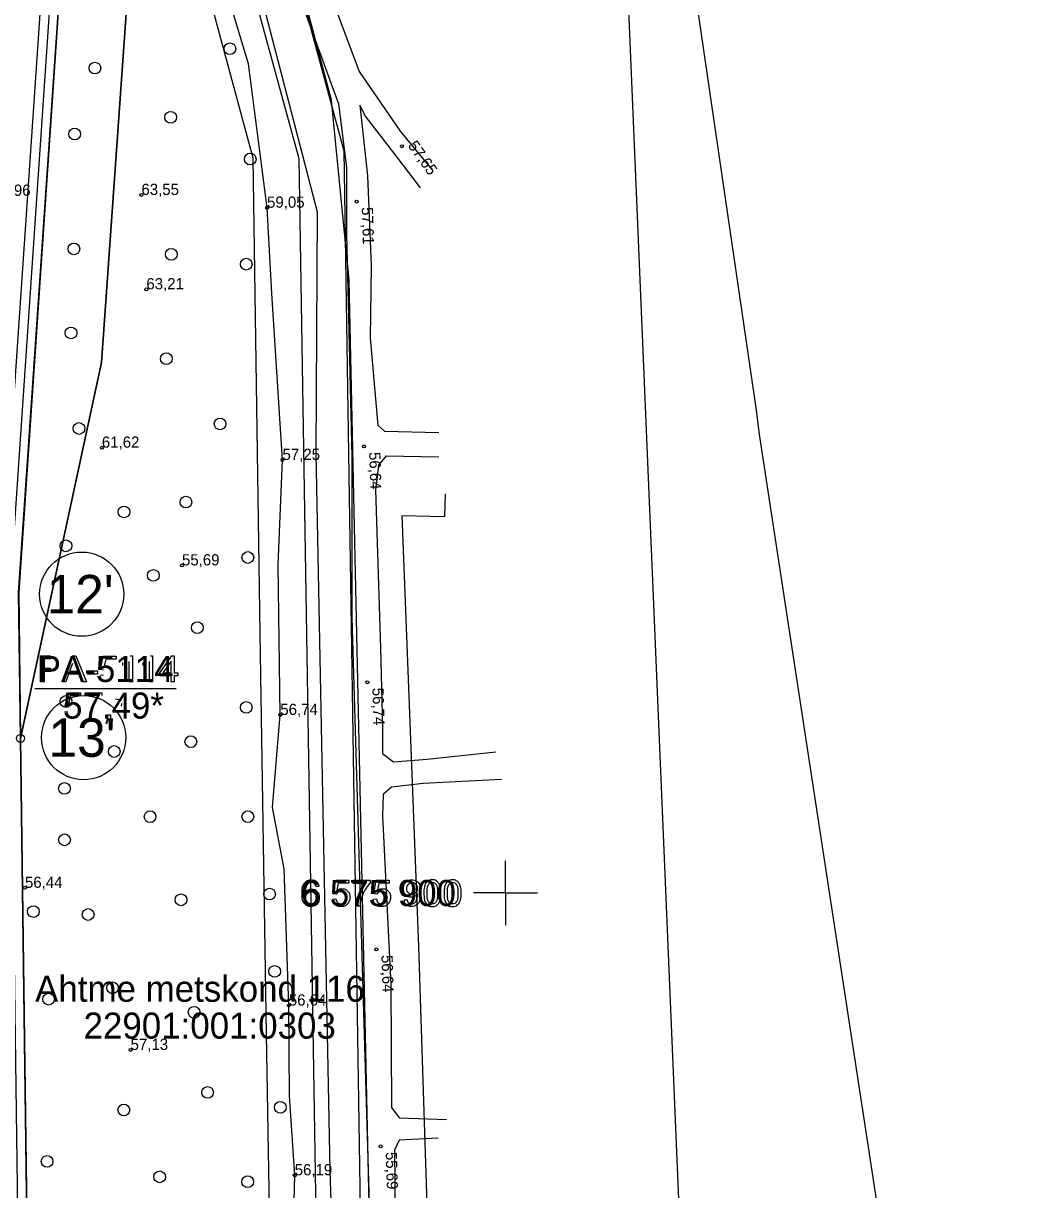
# Model space of a CAD drawing. Extents: x 700746 to 706058, y 6570320 to 6580460.
# Drawn here: x 703294.7 to 703516.5, y 6575835.2 to 6576090 of the extents above; entities that cross this region are included whole.
import ezdxf

# ---------------------------------------------------------------- set-up
doc = ezdxf.new("R2010")
doc.units = 0
for name, color, linetype in [('GEOLPUNKT', 7, 'Continuous'), ('HALJASTUS', 7, 'Continuous'), ('illumineerimisjooned', 7, 'Continuous'), ('Kaitsevöönd', 7, 'Continuous'), ('kataster', 7, 'Continuous'), ('Kataster tekst', 7, 'Continuous'), ('KORGUS-EH2000', 7, 'Continuous'), ('KPOHULIIN', 7, 'Continuous'), ('PIIR', 7, 'Continuous'), ('Plokid', 7, 'Continuous'), ('RELJEEF', 7, 'Continuous'), ('TEE', 7, 'Continuous'), ('Tmaad_maeeraldised_kehtivad', 7, 'Continuous'), ('VORK', 7, 'Continuous'), ('VTRASS', 7, 'Continuous'), ('VWX2_MV_PLOKK', 7, 'Continuous')]:
    doc.layers.add(name, color=color, linetype=linetype)

msp = doc.modelspace()

# ---------------------------------------------------------------- linework, layer by layer
at = {"layer": 'GEOLPUNKT'}
msp.add_line((703297.15, 6575944.7), (703328.06, 6575944.7), dxfattribs=at)
msp.add_line((703297.15, 6575944.7), (703328.06, 6575944.7), dxfattribs=at)
for points in [[(703298.44, 6575946.1), (703298.44, 6575951.8), (703300.59, 6575951.8)], [(703300.65, 6575951.12), (703299.19, 6575951.12), (703299.19, 6575949.09)], [(703303.13, 6575946.1), (703305.32, 6575951.8), (703306.13, 6575951.8), (703308.46, 6575946.1), (703307.6, 6575946.1), (703306.94, 6575947.82), (703304.55, 6575947.82), (703303.93, 6575946.1), (703303.13, 6575946.1)], [(703312.21, 6575948.71), (703311.56, 6575948.79), (703312.11, 6575951.72), (703314.94, 6575951.72), (703314.94, 6575951.05), (703312.67, 6575951.05), (703312.36, 6575949.52)], [(703318.04, 6575951.82), (703318.49, 6575951.82), (703318.49, 6575946.1)], [(703322.47, 6575951.82), (703322.92, 6575951.82), (703322.92, 6575946.1)], [(703326.95, 6575946.1), (703326.95, 6575947.46), (703324.48, 6575947.46), (703324.48, 6575948.1), (703327.08, 6575951.8), (703327.65, 6575951.8), (703327.65, 6575948.1), (703328.42, 6575948.1), (703328.42, 6575947.46), (703327.65, 6575947.46), (703327.65, 6575946.1), (703326.95, 6575946.1)], [(703299.19, 6575949.09), (703300.67, 6575949.09)], [(703305.4, 6575950.11), (703304.77, 6575948.43)], [(703304.77, 6575948.43), (703306.71, 6575948.43), (703306.11, 6575950.02)], [(703308.7, 6575947.81), (703308.7, 6575948.51), (703310.85, 6575948.51), (703310.85, 6575947.81), (703308.7, 6575947.81)], [(703316.39, 6575949.71), (703316.39, 6575950.39)], [(703318.49, 6575946.1), (703317.79, 6575946.1), (703317.79, 6575950.56)], [(703320.82, 6575949.71), (703320.82, 6575950.39)], [(703322.92, 6575946.1), (703322.22, 6575946.1), (703322.22, 6575950.56)], [(703326.95, 6575948.1), (703326.95, 6575950.68), (703325.17, 6575948.1), (703326.95, 6575948.1)], [(703300.65, 6575948.41), (703299.19, 6575948.41), (703299.19, 6575946.1), (703298.44, 6575946.1)], [(703311.43, 6575947.59), (703312.16, 6575947.65)], [(703304.47, 6575940.71), (703303.81, 6575940.79), (703304.36, 6575943.72), (703307.19, 6575943.72), (703307.19, 6575943.05), (703304.92, 6575943.05), (703304.61, 6575941.52)], [(703308.16, 6575943.05), (703308.16, 6575943.72), (703311.85, 6575943.72), (703311.85, 6575943.18)], [(703310.95, 6575943.05), (703308.16, 6575943.05)], [(703315.52, 6575942.22), (703314.82, 6575942.34)], [(703316.13, 6575940.8), (703316.21, 6575941.41)], [(703303.68, 6575939.59), (703304.42, 6575939.65)], [(703312.92, 6575938.1), (703312.92, 6575938.89), (703313.71, 6575938.89), (703313.71, 6575938.1)], [(703314.75, 6575939.61), (703315.45, 6575939.7)], [(703309.67, 6575938.1), (703308.95, 6575938.1)], [(703313.06, 6575936.97), (703312.87, 6575937.27)], [(703313.31, 6575938.1), (703312.92, 6575938.1)]]:
    msp.add_lwpolyline(points, dxfattribs=at)
at = {"layer": 'HALJASTUS'}
for centre in [(703339.8, 6576084.43), (703310.3, 6576080.21), (703326.86, 6576069.47), (703305.88, 6576065.81), (703344.24, 6576060.34), (703305.72, 6576040.71), (703326.99, 6576039.52), (703343.36, 6576037.38), (703305.09, 6576022.36), (703325.92, 6576016.73), (703306.83, 6576001.48), (703337.66, 6576002.49), (703316.66, 6575983.26), (703330.19, 6575985.39), (703303.98, 6575975.84), (703343.71, 6575973.29), (703323.07, 6575969.37), (703332.68, 6575957.97), (703303.98, 6575941.83), (703343.36, 6575940.53), (703331.26, 6575933.05), (703314.53, 6575930.91), (703303.67, 6575922.84), (703322.36, 6575916.67), (703343.71, 6575916.67), (703303.67, 6575911.61), (703348.46, 6575899.75), (703329.12, 6575898.51), (703296.87, 6575895.94), (703308.83, 6575895.3), (703349.57, 6575882.86), (703314.17, 6575879.28), (703300.19, 6575876.8), (703331.97, 6575873.94), (703334.92, 6575856.43), (703350.8, 6575853.18), (703316.63, 6575852.59), (703299.87, 6575841.36), (703324.46, 6575837.99), (703343.68, 6575836.92)]:
    msp.add_circle(centre, 1.28, dxfattribs=at)
at = {"layer": 'illumineerimisjooned'}
msp.add_lwpolyline([(703275.45, 6577071.68), (703358.03, 6576531.93), (703309.57, 6576228.79), (703291.69, 6575965.8), (703292.02, 6575933.77), (703296.8, 6575575.06), (702854, 6575511.22), (702839.23, 6575620.77), (702850.34, 6575977.31), (702784.78, 6576064.06), (702784.62, 6576095.83), (702844.43, 6576209.85), (702855.46, 6576267.3), (702846.53, 6576489.41), (702878.89, 6576547.09), (702976.89, 6576643.26), (702915.33, 6577059.56)], dxfattribs=at)
at = {"layer": 'Kaitsevöönd'}
for points in [[(703404.08, 6576352.03), (703454.73, 6576005.46), (703455.39, 6576000.16), (703516.46, 6575600.64), (703378.76, 6575580.78), (703360.22, 6575577.3), (703249.34, 6575561.08), (703243.21, 6575560.09), (703037.16, 6575527.65), (702916.01, 6575506.13), (702857.92, 6575495.54), (702854.94, 6575495.05), (702852.29, 6575508.95), (702831.77, 6575505.31), (702827.8, 6575504.98), (702697.05, 6575486.77), (702630.85, 6575867.26), (702597.75, 6576057.43)], [(703349.3, 6575779.66), (703347.78, 6575869.24), (703346.43, 6575956.79), (703344.9, 6576060.57), (703308.07, 6576196.97)], [(703328.2, 6576197.08), (703364.66, 6576062.16), (703367.23, 6575896.83), (703368.92, 6575788.66)]]:
    msp.add_lwpolyline(points, dxfattribs=at)
at = {"layer": 'kataster'}
msp.add_lwpolyline([(702852.27, 6575508.89), (702837.26, 6575620.73), (702848.38, 6575976.59), (702782.85, 6576063.35), (702782.57, 6576096.37), (702842.53, 6576210.56), (702853.4, 6576267.5), (702844.46, 6576489.93), (702877.29, 6576548.25), (702974.72, 6576643.9), (702913.57, 6577058.07), (702784.04, 6577102.84), (702746.48, 6577248.7), (702719.69, 6577297.36), (702713.81, 6577334.91), (703089.87, 6577211.79), (703231.53, 6577106.55), (703277.36, 6577072.83), (703360.09, 6576531.99), (703311.6, 6576228.52), (703293.62, 6575965.66), (703298.84, 6575573.29)], close=True, dxfattribs=at)
msp.add_lwpolyline([(702782.57, 6576096.37), (702782.85, 6576063.35), (702848.38, 6575976.59), (702837.26, 6575620.73), (702852.27, 6575508.89), (703298.84, 6575573.29), (703375.63, 6575584.41), (703375.41, 6575624), (703375.74, 6575634.8), (703375.62, 6575689.75), (703370.21, 6575799.42), (703370.29, 6575828.47), (703365.86, 6576033.99), (703361.97, 6576073.22), (703340.19, 6576155.31)], dxfattribs=at)
at = {"layer": 'KORGUS-EH2000'}
for centre in [(703377.36, 6576063.14), (703320.47, 6576052.5), (703367.48, 6576051.05), (703347.91, 6576049.71), (703321.55, 6576031.88), (703311.83, 6575997.28), (703369.11, 6575997.56), (703351.28, 6575994.6), (703329.33, 6575971.57), (703303.02, 6575963.37), (703369.81, 6575946.05), (703350.81, 6575938.9), (703295.03, 6575901.12), (703371.78, 6575887.68), (703352.67, 6575875.41), (703318.1, 6575865.71), (703372.71, 6575844.65), (703353.95, 6575838.32)]:
    msp.add_circle(centre, 0.32, dxfattribs=at)
at = {"layer": 'KPOHULIIN'}
msp.add_lwpolyline([(703335.89, 6576129.69), (703354.83, 6576060.44), (703359.66, 6575761.92), (703361.73, 6575702.19), (703367.45, 6575648.31), (703369.09, 6575627.08), (703349.4, 6575625.31), (703332.6, 6575614.36)], dxfattribs=at)
at = {"layer": 'PIIR'}
for centre, radius in [((703307.43, 6575965.28), 9.2), ((703307.84, 6575933.95), 9.2), ((703294.04, 6575933.77), 0.88)]:
    msp.add_circle(centre, radius, dxfattribs=at)
at = {"layer": 'Plokid'}
for points in [[(703290.64, 6576959.22), (703356.01, 6576531.94), (703307.59, 6576229.01), (703289.69, 6575965.85), (703290.02, 6575933.75), (703291.51, 6575829.64), (703294.32, 6575609.52), (703294.77, 6575576.79), (703154.76, 6575556.6), (703019.06, 6575536.97), (703053.36, 6575698.14), (703145.59, 6575981.92), (703123.04, 6576234.88), (703120.61, 6576749.6), (703011.59, 6576989.47), (702968.34, 6577084.63), (702917.3, 6577059.88)], [(703294.02, 6575933.8), (703311.73, 6576015.89), (703324.97, 6576203.4), (703382.07, 6576503.63), (703406.89, 6576414.25), (703421.79, 6576214.16), (703443.8, 6575689.35), (703467.14, 6575602.46), (703308.25, 6575608.58), (703295.51, 6575829.03)]]:
    msp.add_lwpolyline(points, dxfattribs=at)
at = {"layer": 'RELJEEF'}
msp.add_lwpolyline([(703353.6, 6575824.14), (703353.95, 6575838.32), (703352.79, 6575855.65), (703352.67, 6575875.41), (703351.63, 6575905.3), (703349.07, 6575918.67), (703350.81, 6575938.9), (703350.35, 6575971.69), (703351.28, 6575994.6), (703348.95, 6576030.99), (703347.91, 6576049.71), (703343.84, 6576081.11), (703335.7, 6576108.2)], dxfattribs=at)
at = {"layer": 'TEE'}
for points in [[(703352.19, 6576141.74), (703360.69, 6576106.32), (703363.13, 6576092.48), (703368.01, 6576079.46), (703376.96, 6576066.44), (703383.87, 6576058.09)], [(703345.4, 6576137.9), (703350.99, 6576113.18), (703356.45, 6576091.79), (703363.54, 6576072.37), (703365.29, 6576058.53), (703365.29, 6576044), (703366.45, 6575995.39), (703366.45, 6575960.16), (703371.65, 6575782.87), (703375.48, 6575700.43)], [(703381.43, 6576054.03), (703376.35, 6576060.74), (703369.43, 6576069.69), (703368.21, 6576072.14), (703369.84, 6576056.67), (703370.65, 6576037.14), (703370.45, 6576021.26), (703371.87, 6576004.58), (703372.14, 6576002.21)], [(703372.14, 6576002.21), (703373.56, 6576000.86), (703385.41, 6576000.63)], [(703372.28, 6575993.42), (703374.02, 6575995.51), (703377.74, 6575995.4), (703385.41, 6575995.28)], [(703372.28, 6575993.42), (703371.58, 6575988.07), (703372.69, 6575953.45), (703373.1, 6575936.16), (703373.1, 6575930.46), (703375.54, 6575928.63), (703382.86, 6575929.24), (703397.91, 6575930.87)], [(703399.13, 6575924.76), (703382.04, 6575923.95), (703375.13, 6575923.13), (703373.3, 6575921.51), (703373.1, 6575916.83), (703374.93, 6575880), (703375.13, 6575853.14), (703376.76, 6575850.9), (703387.13, 6575850.49)], [(703385.3, 6575846.42), (703376.76, 6575846.01), (703375.74, 6575843.78), (703376.15, 6575799.42), (703377.16, 6575762.58), (703378.18, 6575759.94), (703382.45, 6575758.72), (703392.62, 6575759.74)]]:
    msp.add_lwpolyline(points, dxfattribs=at)
at = {"layer": 'Tmaad_maeeraldised_kehtivad'}
msp.add_lwpolyline([(703277.3, 6577072.8), (703360.06, 6576531.93), (703311.56, 6576228.56), (703293.69, 6575965.74), (703294.02, 6575933.8), (703298.82, 6575573.33), (702852.29, 6575508.95), (702837.23, 6575620.66), (702848.32, 6575976.66), (702782.78, 6576063.39), (702782.61, 6576096.32), (702842.53, 6576210.52), (702853.45, 6576267.45), (702844.51, 6576489.89), (702877.28, 6576548.31), (702974.76, 6576643.97), (702913.53, 6577058.07)], dxfattribs=at)
at = {"layer": 'VORK'}
for q in [(703400, 6575907), (703400, 6575907), (703400, 6575907), (703400, 6575907), (703393, 6575900), (703393, 6575900), (703407, 6575900), (703400, 6575893), (703407, 6575900), (703400, 6575893)]:
    msp.add_line((703400, 6575900), q, dxfattribs=at)
for points in [[(703363.02, 6575899.76), (703362.36, 6575899.85), (703362.91, 6575902.77), (703365.75, 6575902.77), (703365.75, 6575902.11), (703363.47, 6575902.11), (703363.17, 6575900.58)], [(703366.71, 6575902.1), (703366.71, 6575902.77), (703370.4, 6575902.77), (703370.4, 6575902.23)], [(703371.87, 6575899.76), (703371.22, 6575899.85), (703371.77, 6575902.77), (703374.6, 6575902.77), (703374.6, 6575902.11), (703372.33, 6575902.11), (703372.02, 6575900.58)], [(703359.23, 6575901.45), (703358.54, 6575901.39)], [(703369.5, 6575902.1), (703366.71, 6575902.1)], [(703362.24, 6575898.64), (703362.97, 6575898.7)], [(703371.09, 6575898.64), (703371.82, 6575898.7)], [(703377.83, 6575898.47), (703378.51, 6575898.53)], [(703368.23, 6575897.15), (703367.51, 6575897.15)]]:
    msp.add_lwpolyline(points, dxfattribs=at)
for points in [[(703358.54, 6575901.39), (703358.44, 6575901.81), (703358.27, 6575902), (703357.99, 6575902.3), (703357.57, 6575902.3), (703357.24, 6575902.3), (703356.98, 6575902.11), (703356.65, 6575901.87), (703356.46, 6575901.41), (703356.27, 6575900.94), (703356.26, 6575900.09), (703356.51, 6575900.47), (703356.88, 6575900.66), (703357.25, 6575900.85), (703357.65, 6575900.85), (703358.35, 6575900.85), (703358.84, 6575900.33), (703359.33, 6575899.82), (703359.33, 6575899), (703359.33, 6575898.46), (703359.1, 6575898), (703358.87, 6575897.54), (703358.47, 6575897.3), (703358.06, 6575897.05), (703357.55, 6575897.05), (703356.67, 6575897.05), (703356.12, 6575897.7), (703355.57, 6575898.34), (703355.57, 6575899.82), (703355.57, 6575901.47), (703356.18, 6575902.22), (703356.71, 6575902.87), (703357.61, 6575902.87), (703358.29, 6575902.87), (703358.72, 6575902.49), (703359.15, 6575902.11), (703359.23, 6575901.45)], [(703378.51, 6575898.53), (703378.59, 6575898.05), (703378.83, 6575897.84), (703379.07, 6575897.63), (703379.45, 6575897.63), (703379.77, 6575897.63), (703380.02, 6575897.77), (703380.26, 6575897.92), (703380.41, 6575898.17), (703380.57, 6575898.42), (703380.67, 6575898.84), (703380.78, 6575899.26), (703380.78, 6575899.69), (703380.78, 6575899.74), (703380.77, 6575899.83), (703380.56, 6575899.5), (703380.2, 6575899.29), (703379.84, 6575899.08), (703379.41, 6575899.08), (703378.71, 6575899.08), (703378.22, 6575899.59), (703377.73, 6575900.11), (703377.73, 6575900.95), (703377.73, 6575901.81), (703378.24, 6575902.34), (703378.75, 6575902.87), (703379.52, 6575902.87), (703380.07, 6575902.87), (703380.53, 6575902.57), (703381, 6575902.27), (703381.23, 6575901.72), (703381.47, 6575901.16), (703381.47, 6575900.11), (703381.47, 6575899.02), (703381.24, 6575898.38), (703381, 6575897.73), (703380.53, 6575897.39), (703380.06, 6575897.05), (703379.43, 6575897.05), (703378.76, 6575897.05), (703378.34, 6575897.42), (703377.92, 6575897.8), (703377.83, 6575898.47)], [(703382.15, 6575899.96), (703382.15, 6575900.97), (703382.36, 6575901.59), (703382.57, 6575902.2), (703382.98, 6575902.54), (703383.39, 6575902.87), (703384.01, 6575902.87), (703384.47, 6575902.87), (703384.82, 6575902.69), (703385.16, 6575902.5), (703385.39, 6575902.15), (703385.61, 6575901.8), (703385.74, 6575901.31), (703385.87, 6575900.81), (703385.87, 6575899.96), (703385.87, 6575898.96), (703385.66, 6575898.34), (703385.46, 6575897.72), (703385.05, 6575897.39), (703384.64, 6575897.05), (703384.01, 6575897.05), (703383.19, 6575897.05), (703382.72, 6575897.64), (703382.15, 6575898.35), (703382.15, 6575899.96)], [(703386.58, 6575899.96), (703386.58, 6575900.97), (703386.79, 6575901.59), (703387, 6575902.2), (703387.41, 6575902.54), (703387.82, 6575902.87), (703388.44, 6575902.87), (703388.9, 6575902.87), (703389.24, 6575902.69), (703389.59, 6575902.5), (703389.82, 6575902.15), (703390.04, 6575901.8), (703390.17, 6575901.31), (703390.3, 6575900.81), (703390.3, 6575899.96), (703390.3, 6575898.96), (703390.09, 6575898.34), (703389.88, 6575897.72), (703389.47, 6575897.39), (703389.06, 6575897.05), (703388.44, 6575897.05), (703387.62, 6575897.05), (703387.15, 6575897.64), (703386.58, 6575898.35), (703386.58, 6575899.96)], [(703356.37, 6575899), (703356.37, 6575898.63), (703356.52, 6575898.3), (703356.68, 6575897.97), (703356.95, 6575897.8), (703357.23, 6575897.63), (703357.53, 6575897.63), (703357.98, 6575897.63), (703358.29, 6575897.98), (703358.61, 6575898.34), (703358.61, 6575898.96), (703358.61, 6575899.55), (703358.3, 6575899.89), (703357.98, 6575900.23), (703357.5, 6575900.23), (703357.03, 6575900.23), (703356.7, 6575899.89), (703356.37, 6575899.55), (703356.37, 6575899)], [(703363.17, 6575900.58), (703363.68, 6575900.93), (703364.24, 6575900.93), (703364.99, 6575900.93), (703365.5, 6575900.41), (703366.02, 6575899.9), (703366.02, 6575899.08), (703366.02, 6575898.31), (703365.56, 6575897.75), (703365.02, 6575897.05), (703364.07, 6575897.05), (703363.29, 6575897.05), (703362.8, 6575897.49), (703362.31, 6575897.92), (703362.24, 6575898.64)], [(703362.97, 6575898.7), (703363.05, 6575898.17), (703363.35, 6575897.9), (703363.64, 6575897.63), (703364.07, 6575897.63), (703364.58, 6575897.63), (703364.92, 6575898.01), (703365.27, 6575898.39), (703365.27, 6575899.02), (703365.27, 6575899.62), (703364.94, 6575899.97), (703364.6, 6575900.32), (703364.06, 6575900.32), (703363.71, 6575900.32), (703363.44, 6575900.16), (703363.17, 6575900.01), (703363.02, 6575899.76)], [(703367.51, 6575897.15), (703367.52, 6575897.82), (703367.77, 6575898.77), (703368.02, 6575899.73), (703368.49, 6575900.61), (703368.97, 6575901.49), (703369.5, 6575902.1)], [(703370.4, 6575902.23), (703369.85, 6575901.65), (703369.32, 6575900.69), (703368.79, 6575899.73), (703368.49, 6575898.71), (703368.28, 6575898), (703368.23, 6575897.15)], [(703372.02, 6575900.58), (703372.53, 6575900.93), (703373.1, 6575900.93), (703373.84, 6575900.93), (703374.36, 6575900.41), (703374.87, 6575899.9), (703374.87, 6575899.08), (703374.87, 6575898.31), (703374.42, 6575897.75), (703373.87, 6575897.05), (703372.92, 6575897.05), (703372.14, 6575897.05), (703371.65, 6575897.49), (703371.16, 6575897.92), (703371.09, 6575898.64)], [(703371.82, 6575898.7), (703371.91, 6575898.17), (703372.2, 6575897.9), (703372.5, 6575897.63), (703372.92, 6575897.63), (703373.43, 6575897.63), (703373.78, 6575898.01), (703374.13, 6575898.39), (703374.13, 6575899.02), (703374.13, 6575899.62), (703373.79, 6575899.97), (703373.46, 6575900.32), (703372.91, 6575900.32), (703372.57, 6575900.32), (703372.3, 6575900.16), (703372.03, 6575900.01), (703371.87, 6575899.76)], [(703380.7, 6575900.98), (703380.7, 6575901.58), (703380.38, 6575901.94), (703380.06, 6575902.29), (703379.61, 6575902.29), (703379.14, 6575902.29), (703378.79, 6575901.91), (703378.45, 6575901.53), (703378.45, 6575900.92), (703378.45, 6575900.38), (703378.78, 6575900.04), (703379.1, 6575899.7), (703379.59, 6575899.7), (703380.07, 6575899.7), (703380.38, 6575900.04), (703380.7, 6575900.38), (703380.7, 6575900.98)], [(703382.88, 6575899.96), (703382.88, 6575898.55), (703383.2, 6575898.09), (703383.53, 6575897.63), (703384.01, 6575897.63), (703384.49, 6575897.63), (703384.82, 6575898.09), (703385.15, 6575898.56), (703385.15, 6575899.96), (703385.15, 6575901.37), (703384.82, 6575901.83), (703384.49, 6575902.29), (703384, 6575902.29), (703383.52, 6575902.29), (703383.24, 6575901.88), (703382.88, 6575901.36), (703382.88, 6575899.96)], [(703387.3, 6575899.96), (703387.3, 6575898.55), (703387.63, 6575898.09), (703387.96, 6575897.63), (703388.44, 6575897.63), (703388.92, 6575897.63), (703389.25, 6575898.09), (703389.58, 6575898.56), (703389.58, 6575899.96), (703389.58, 6575901.37), (703389.25, 6575901.83), (703388.92, 6575902.29), (703388.43, 6575902.29), (703387.95, 6575902.29), (703387.66, 6575901.88), (703387.3, 6575901.36), (703387.3, 6575899.96)]]:
    msp.add_open_spline(points, degree=3, dxfattribs=at)
at = {"layer": 'VTRASS'}
for points in [[(703316.4, 6576213.76), (703332.34, 6576150.65), (703344.67, 6576103.5), (703358.89, 6576048.78)], [(703358.89, 6576048.78), (703358.55, 6575996.07), (703361.64, 6575839.38), (703364.1, 6575762.99), (703365.67, 6575650.23), (703390.77, 6575650.9)], [(703402.03, 6575627.5), (703402.03, 6575627.5), (703401.83, 6575627.69), (703402, 6575678.56), (703385.44, 6575678.62), (703383.41, 6575747.02), (703383.24, 6575820.71), (703381.05, 6575888.32), (703377.39, 6575982.5), (703386.77, 6575982.28), (703386.89, 6575987.19)]]:
    msp.add_lwpolyline(points, dxfattribs=at)
at = {"layer": 'VWX2_MV_PLOKK'}
for points in [[(703044.07, 6577449.05), (703125.37, 6577441.7), (703167.08, 6577172.26), (703170.22, 6577152.1), (703231.53, 6577106.55), (703277.36, 6577072.83), (703360.09, 6576531.99), (703311.6, 6576228.52), (703293.62, 6575965.66), (703294.04, 6575933.77), (703295.43, 6575829.7), (703298.36, 6575609.6), (703298.84, 6575573.29), (703155.29, 6575552.59), (703145.59, 6575981.92), (703123.04, 6576234.88), (703120.61, 6576749.6), (703011.59, 6576989.47), (703015.74, 6577110.88), (702996.73, 6577210.32)], [(703170.54, 6577151.86), (703296.17, 6577067.83), (703382.07, 6576503.63), (703324.97, 6576203.4), (703311.73, 6576015.89), (703294.04, 6575933.77), (703293.62, 6575965.66), (703311.6, 6576228.52), (703360.09, 6576531.99), (703277.36, 6577072.83), (703231.53, 6577106.55)], [(703443.86, 6575689.39), (703467.13, 6575602.53), (703308.24, 6575608.65), (703295.44, 6575828.99), (703294.04, 6575933.77), (703311.73, 6576015.89), (703324.97, 6576203.33), (703382.07, 6576503.63), (703406.94, 6576414.24), (703421.77, 6576214.18)]]:
    msp.add_lwpolyline(points, close=True, dxfattribs=at)
msp.add_lwpolyline([(703187.67, 6576999.67), (703190.39, 6576656.32), (703340.88, 6576657.54), (703360.09, 6576531.99), (703311.6, 6576228.52), (703293.62, 6575965.66), (703294.04, 6575933.77), (703295.43, 6575829.7), (703298.36, 6575609.6), (703298.84, 6575573.29), (703155.29, 6575552.59), (703018.17, 6575532.81), (703053.36, 6575698.14), (703145.59, 6575981.92), (703123.04, 6576234.88), (703120.61, 6576749.6), (703011.59, 6576989.47)], dxfattribs=at)
msp.add_lwpolyline([(703187.67, 6576999.67), (703190.39, 6576656.32), (703340.88, 6576657.54), (703360.09, 6576531.99), (703311.6, 6576228.52), (703293.62, 6575965.66), (703294.04, 6575933.77), (703295.43, 6575829.7), (703298.36, 6575609.6), (703298.84, 6575573.29), (703155.29, 6575552.59), (703018.17, 6575532.81), (703053.36, 6575698.14), (703145.59, 6575981.92), (703123.04, 6576234.88), (703120.61, 6576749.6), (703011.59, 6576989.47)], dxfattribs=at)

# ---------------------------------------------------------------- texts
at = {"layer": 'GEOLPUNKT'}
for s, p in [('PA-5114', (703297.82, 6575946.1)), ('57,49*', (703303.35, 6575938.1))]:
    msp.add_text(s, height=5.7, dxfattribs=at).set_placement(p)
at = {"layer": 'Kataster tekst'}
for s, p in [('Ahtme metskond 116', (703297.24, 6575876.23)), ('22901:001:0303', (703307.83, 6575868.18))]:
    msp.add_text(s, height=5.7, dxfattribs=at).set_placement(p)
at = {"layer": 'KORGUS-EH2000'}
for s, rotation, p in [('57,65 ', 305.414, (703378.57, 6576063.26)), ('57,61 ', 271.7994, (703368.59, 6576049.8)), ('56,64 ', 271.7994, (703370.21, 6575996.31)), ('56,74 ', 271.7994, (703370.91, 6575944.8)), ('56,64 ', 271.7994, (703372.89, 6575886.43)), ('55,69 ', 271.7994, (703373.82, 6575843.4))]:
    msp.add_text(s, height=2.45, rotation=rotation, dxfattribs=at).set_placement(p)
for s, p in [('55,96 ', (703288.06, 6576052.31)), ('63,55 ', (703320.47, 6576052.5)), ('59,05 ', (703347.91, 6576049.71)), ('63,21 ', (703321.55, 6576031.88)), ('61,62 ', (703311.83, 6575997.28)), ('57,25 ', (703351.28, 6575994.6)), ('55,69 ', (703329.33, 6575971.57)), ('56,74 ', (703350.81, 6575938.9)), ('56,44 ', (703295.03, 6575901.12)), ('56,64 ', (703352.67, 6575875.41)), ('57,13 ', (703318.1, 6575865.71)), ('56,19 ', (703353.95, 6575838.32))]:
    msp.add_text(s, height=2.45, dxfattribs=at).set_placement(p)
at = {"layer": 'PIIR'}
for s, p in [("12'", (703299.76, 6575961.08)), ("13'", (703300.18, 6575929.75))]:
    msp.add_text(s, height=8.4, dxfattribs=at).set_placement(p)
at = {"layer": 'VORK'}
msp.add_text('6 575 900', height=5.7, dxfattribs=at).set_placement((703355.27, 6575897.15))

doc.saveas('drawing.dxf')
